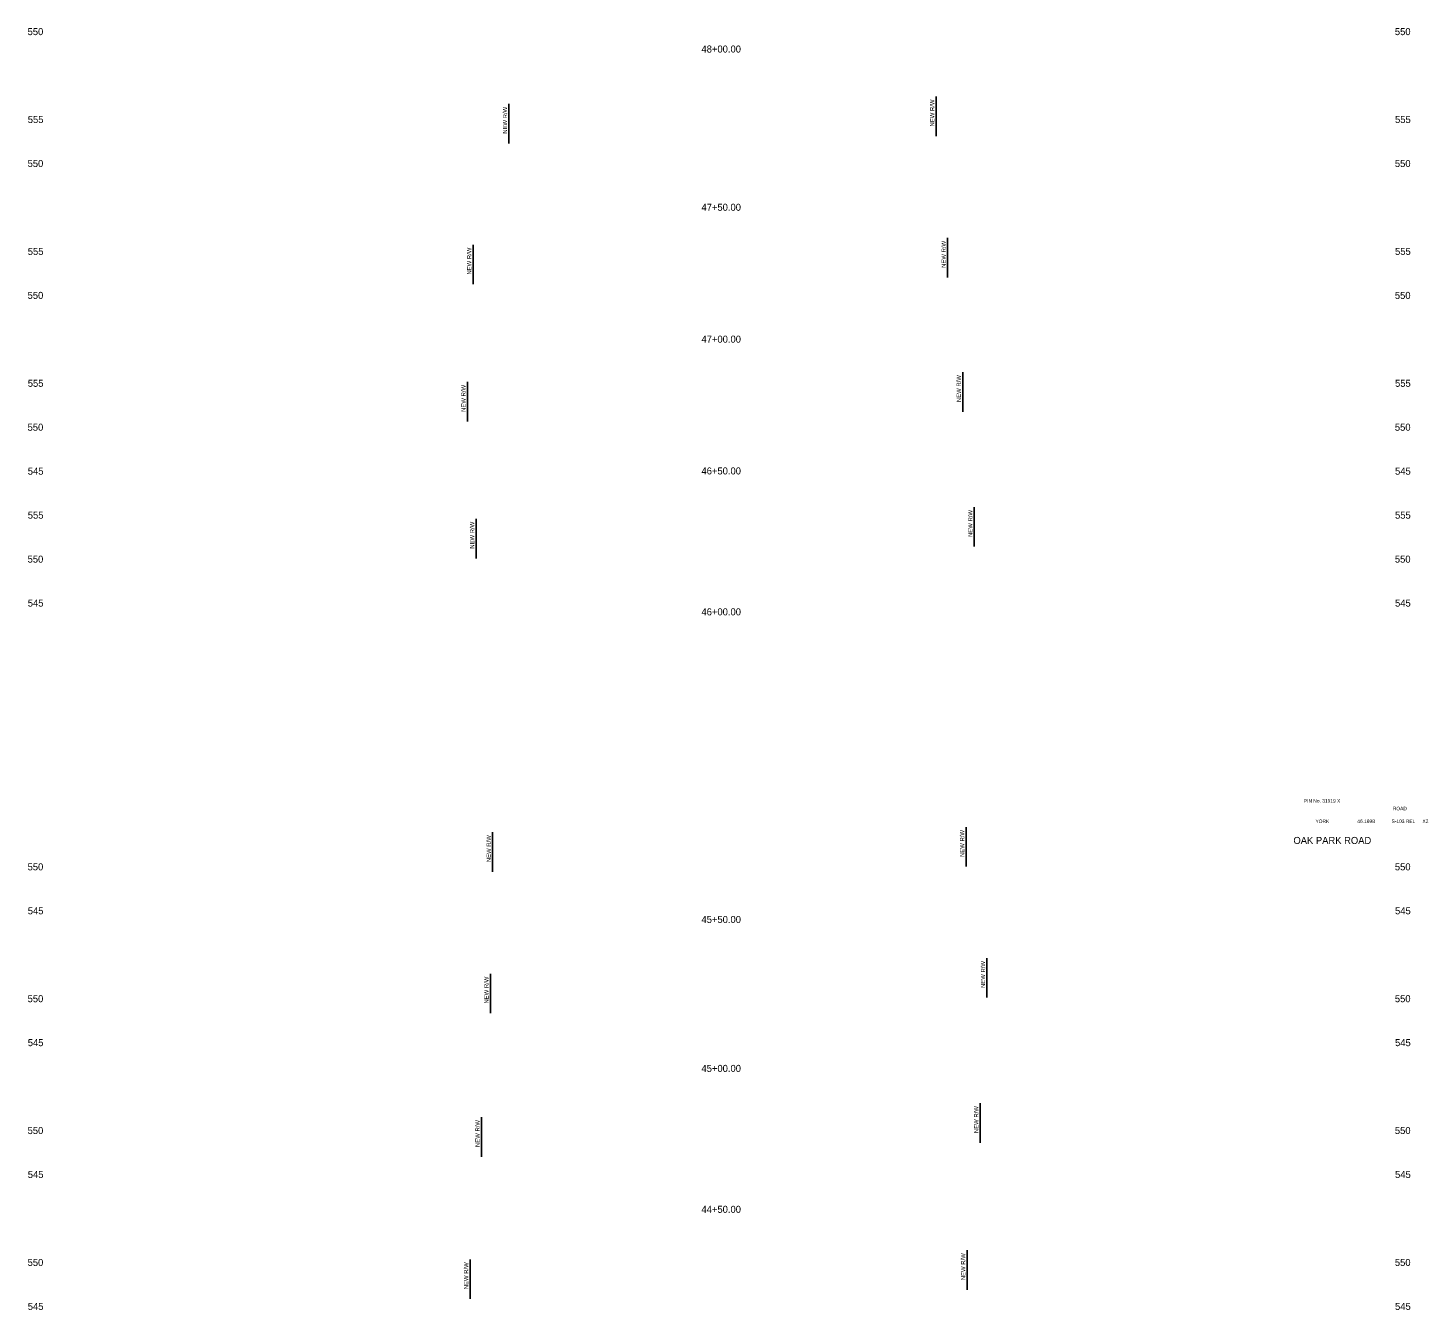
# Model space of a CAD drawing. Extents: x 1001 to 1161, y 1005 to 3518.
# Drawn here: x 1001.2 to 1160.4, y 1160.1 to 1305.9 of the extents above; entities that cross this region are included whole.
import ezdxf

# ---------------------------------------------------------------- set-up
doc = ezdxf.new("R2010")
doc.units = 0
for name, color, linetype in [('RD_SHT_TX', 7, 'Continuous'), ('RD_XS_NewRW', 7, 'Continuous'), ('RD_XS_TX_Elev_EX', 7, 'Continuous'), ('RD_XS_TX_Station', 7, 'Continuous')]:
    doc.layers.add(name, color=color, linetype=linetype)

msp = doc.modelspace()

# ---------------------------------------------------------------- linework, layer by layer
at = {"layer": 'RD_XS_NewRW'}
for p, q in [((1104.47, 1298.11), (1104.47, 1293.61)), ((1055.88, 1297.28), (1055.88, 1292.78)), ((1105.77, 1282.03), (1105.77, 1277.53)), ((1051.82, 1281.26), (1051.82, 1276.76)), ((1107.49, 1266.76), (1107.49, 1262.26)), ((1051.16, 1265.65), (1051.16, 1261.15)), ((1052.14, 1250.08), (1052.14, 1245.58)), ((1108.8, 1251.42), (1108.8, 1246.92)), ((1107.87, 1215.02), (1107.87, 1210.52)), ((1054.03, 1214.43), (1054.03, 1209.93)), ((1110.24, 1200.12), (1110.24, 1195.62)), ((1053.77, 1198.34), (1053.77, 1193.84)), ((1109.47, 1183.6), (1109.47, 1179.1)), ((1052.76, 1182.03), (1052.76, 1177.53)), ((1051.46, 1165.85), (1051.46, 1161.35)), ((1107.99, 1166.88), (1107.99, 1162.38))]:
    msp.add_line(p, q, dxfattribs=at)

# ---------------------------------------------------------------- texts
at = {"layer": 'RD_SHT_TX'}
for s, height, p in [('PIN No. 31919 X', 0.4, (1146.29, 1217.8)), ('ROAD', 0.4, (1156.41, 1216.93)), ('YORK', 0.4, (1147.61, 1215.48)), ('46.169B', 0.4, (1152.37, 1215.48)), ('S-103 REL', 0.4, (1156.26, 1215.48)), ('X2', 0.4, (1159.78, 1215.48)), ('OAK PARK ROAD', 0.8, (1145.1, 1213.1))]:
    msp.add_text(s, height=height, dxfattribs=at).set_placement(p)
at = {"layer": 'RD_XS_NewRW'}
for p in [(1104.27, 1294.71), (1055.68, 1293.88), (1051.61, 1277.86), (1105.57, 1278.63), (1107.29, 1263.36), (1050.96, 1262.25), (1108.6, 1248.02), (1051.94, 1246.68), (1053.83, 1211.03), (1107.67, 1211.62), (1110.04, 1196.72), (1053.56, 1194.94), (1109.27, 1180.21), (1052.56, 1178.63), (1107.79, 1163.48), (1051.26, 1162.45)]:
    msp.add_text('NEW R/W ', height=0.488, rotation=90, dxfattribs=at).set_placement(p)
at = {"layer": 'RD_XS_TX_Elev_EX'}
for s, p in [('550', (1001.14, 1305.1)), ('550', (1156.64, 1305.1)), ('555', (1001.16, 1295.1)), ('555', (1156.66, 1295.1)), ('550', (1001.14, 1290.1)), ('550', (1156.64, 1290.1)), ('555', (1001.16, 1280.1)), ('555', (1156.66, 1280.1)), ('550', (1001.14, 1275.1)), ('550', (1156.64, 1275.1)), ('555', (1001.16, 1265.1)), ('555', (1156.66, 1265.1)), ('550', (1001.14, 1260.1)), ('550', (1156.64, 1260.1)), ('545', (1001.16, 1255.1)), ('545', (1156.66, 1255.1)), ('555', (1001.16, 1250.1)), ('555', (1156.66, 1250.1)), ('550', (1001.14, 1245.1)), ('550', (1156.64, 1245.1)), ('545', (1001.16, 1240.1)), ('545', (1156.66, 1240.1)), ('550', (1001.14, 1210.1)), ('550', (1156.64, 1210.1)), ('545', (1001.16, 1205.1)), ('545', (1156.66, 1205.1)), ('550', (1001.14, 1195.1)), ('550', (1156.64, 1195.1)), ('545', (1001.16, 1190.1)), ('545', (1156.66, 1190.1)), ('550', (1001.14, 1180.1)), ('550', (1156.64, 1180.1)), ('545', (1001.16, 1175.1)), ('545', (1156.66, 1175.1)), ('550', (1001.14, 1165.1)), ('550', (1156.64, 1165.1)), ('545', (1001.16, 1160.1)), ('545', (1156.66, 1160.1))]:
    msp.add_text(s, height=0.8, dxfattribs=at).set_placement(p)
at = {"layer": 'RD_XS_TX_Station'}
for s, p in [('48+00.00', (1077.78, 1303.12)), ('47+50.00', (1077.78, 1285.12)), ('47+00.00', (1077.78, 1270.12)), ('46+50.00', (1077.78, 1255.13)), ('46+00.00', (1077.78, 1239.1)), ('45+50.00', (1077.78, 1204.11)), ('45+00.00', (1077.78, 1187.17)), ('44+50.00', (1077.78, 1171.14))]:
    msp.add_text(s, height=0.8, dxfattribs=at).set_placement(p)

doc.saveas('drawing.dxf')
